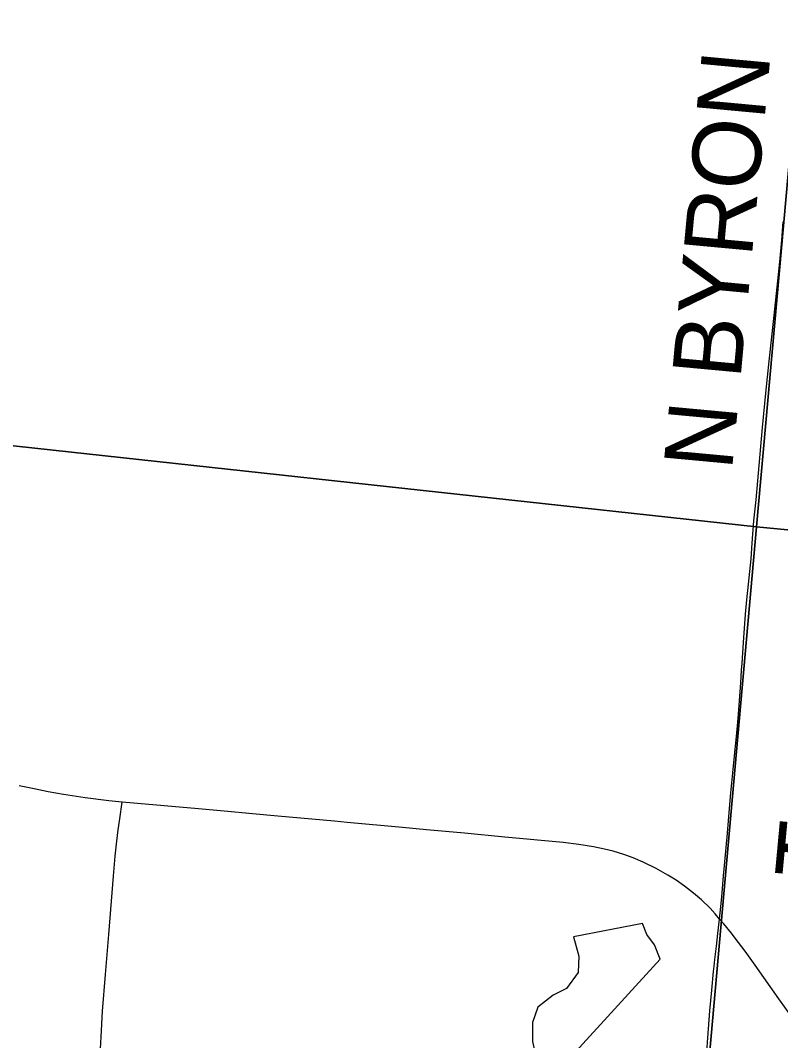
# Model space of a CAD drawing. Extents: x 0 to 34, y 0 to 22.
# Drawn here: x 27.523 to 28.153, y 17.021 to 17.866 of the extents above; entities that cross this region are included whole.
import ezdxf

# ---------------------------------------------------------------- set-up
doc = ezdxf.new("R2010")
doc.units = 0
for name, color, linetype in [('GM_X_County_Road', 7, 'Continuous'), ('GM_X_Minor_Lake', 7, 'Continuous'), ('GM_X_Section', 7, 'Continuous'), ('GM_X_State_Route', 7, 'Continuous'), ('GM_X_Township_Road', 7, 'Continuous'), ('GM_X_Township_Road_Text', 7, 'Continuous')]:
    doc.layers.add(name, color=color, linetype=linetype)

msp = doc.modelspace()

# ---------------------------------------------------------------- linework, layer by layer
at = {"layer": 'GM_X_County_Road'}
msp.add_lwpolyline([(27.58971, 17.01445), (27.59014, 17.02438), (27.59136, 17.04546), (27.5937, 17.07588), (27.5965, 17.10903), (27.60045, 17.15735), (27.60172, 17.17392), (27.603, 17.18642), (27.60428, 17.1956), (27.60555, 17.20491), (27.60741, 17.21866)], dxfattribs=at)
at = {"layer": 'GM_X_Minor_Lake'}
for points in [[(27.98128, 17.10714), (27.98589, 17.09109), (27.98524, 17.07744), (27.97552, 17.06435), (27.96443, 17.05889), (27.95175, 17.0489), (27.94733, 17.03608), (27.9474, 17.02052), (27.95054, 17.00678), (27.96061, 16.99974), (27.97048, 17.00106), (27.98319, 17.01218), (28.0532, 17.08856), (28.04852, 17.10043), (28.04225, 17.10891), (28.03865, 17.1181)], [(28.03865, 17.1181), (27.98128, 17.10714)]]:
    msp.add_lwpolyline(points, dxfattribs=at)
at = {"layer": 'GM_X_Section'}
for points in [[(27.24577, 18.5491), (28.22311, 18.45295), (28.13294, 17.44672), (27.13988, 17.55487)], [(29.22323, 18.35984), (29.12771, 17.35066), (28.13294, 17.44672), (28.22311, 18.45295)], [(27.13988, 17.55487), (28.13294, 17.44672), (28.04353, 16.442), (27.03603, 16.54895)], [(28.13294, 17.44672), (29.12771, 17.35066), (29.04197, 16.33867), (28.04353, 16.442)]]:
    msp.add_lwpolyline(points, close=True, dxfattribs=at)
at = {"layer": 'GM_X_State_Route'}
for points in [[(27.60741, 17.21866), (27.59656, 17.21978), (27.57681, 17.22226), (27.55898, 17.22499), (27.54611, 17.22726), (27.53452, 17.22957), (27.52226, 17.23225)], [(28.10235, 17.12185), (28.09885, 17.12605), (28.09451, 17.1307), (28.08729, 17.1377), (28.08072, 17.14335), (28.07339, 17.14904), (28.06631, 17.15401), (28.05947, 17.15822), (28.04972, 17.16361), (28.03918, 17.16885), (28.03069, 17.17258), (28.02316, 17.17534), (28.0143, 17.17802), (28.0071, 17.17981), (27.998, 17.18166), (27.98576, 17.18361), (27.97283, 17.18516), (27.92457, 17.18966), (27.89116, 17.19288), (27.8596, 17.19569), (27.83978, 17.19749), (27.794, 17.20182), (27.78348, 17.20277), (27.73643, 17.20698), (27.71539, 17.20901), (27.69189, 17.21122), (27.67084, 17.21312), (27.64236, 17.21568), (27.60741, 17.21866)], [(28.16405, 17.03806), (28.15137, 17.05568), (28.13175, 17.08358), (28.12349, 17.0952), (28.11534, 17.10611), (28.11228, 17.11), (28.10833, 17.11478), (28.10585, 17.11783), (28.10235, 17.12185)]]:
    msp.add_lwpolyline(points, dxfattribs=at)
at = {"layer": 'GM_X_Township_Road'}
for points in [[(28.13078, 17.45142), (28.13256, 17.46894), (28.13795, 17.52892), (28.14073, 17.55732), (28.14342, 17.58389), (28.14749, 17.62154), (28.15003, 17.645), (28.15227, 17.66602), (28.15387, 17.68397), (28.15504, 17.69924)], [(28.10235, 17.12185), (28.10344, 17.13226), (28.10424, 17.14031), (28.10571, 17.15762), (28.10644, 17.16628), (28.10887, 17.19286), (28.11056, 17.21327), (28.11172, 17.22623), (28.1133, 17.24283), (28.11481, 17.25694), (28.11652, 17.27295), (28.11782, 17.28778), (28.11992, 17.31749), (28.12062, 17.32801), (28.12105, 17.33357), (28.12222, 17.35088), (28.12376, 17.37439), (28.12483, 17.38612), (28.12629, 17.39906), (28.12747, 17.40955), (28.12851, 17.42007), (28.12948, 17.43307), (28.13078, 17.45142)], [(28.07421, 16.81067), (28.07758, 16.84239), (28.08061, 16.87641), (28.08227, 16.8956), (28.08318, 16.90675), (28.08541, 16.93275), (28.08739, 16.95493), (28.08816, 16.96788), (28.08936, 16.98272), (28.09036, 16.9951), (28.091, 17.00315), (28.09141, 17.00809), (28.09271, 17.02353), (28.09435, 17.04574), (28.09584, 17.06298), (28.09747, 17.07835), (28.09794, 17.08267), (28.09857, 17.08822), (28.09993, 17.09932), (28.10099, 17.1098), (28.10235, 17.12185)]]:
    msp.add_lwpolyline(points, dxfattribs=at)

# ---------------------------------------------------------------- texts
at = {"layer": 'GM_X_Township_Road_Text'}
for s, height, rotation, p in [('N BYRON', 0.056818, 84.69651, (28.11259, 17.49245)), ('T', 0.05682, 84.69537, (28.20472, 17.15311))]:
    msp.add_text(s, height=height, rotation=rotation, dxfattribs=at).set_placement(p)

doc.saveas('drawing.dxf')
